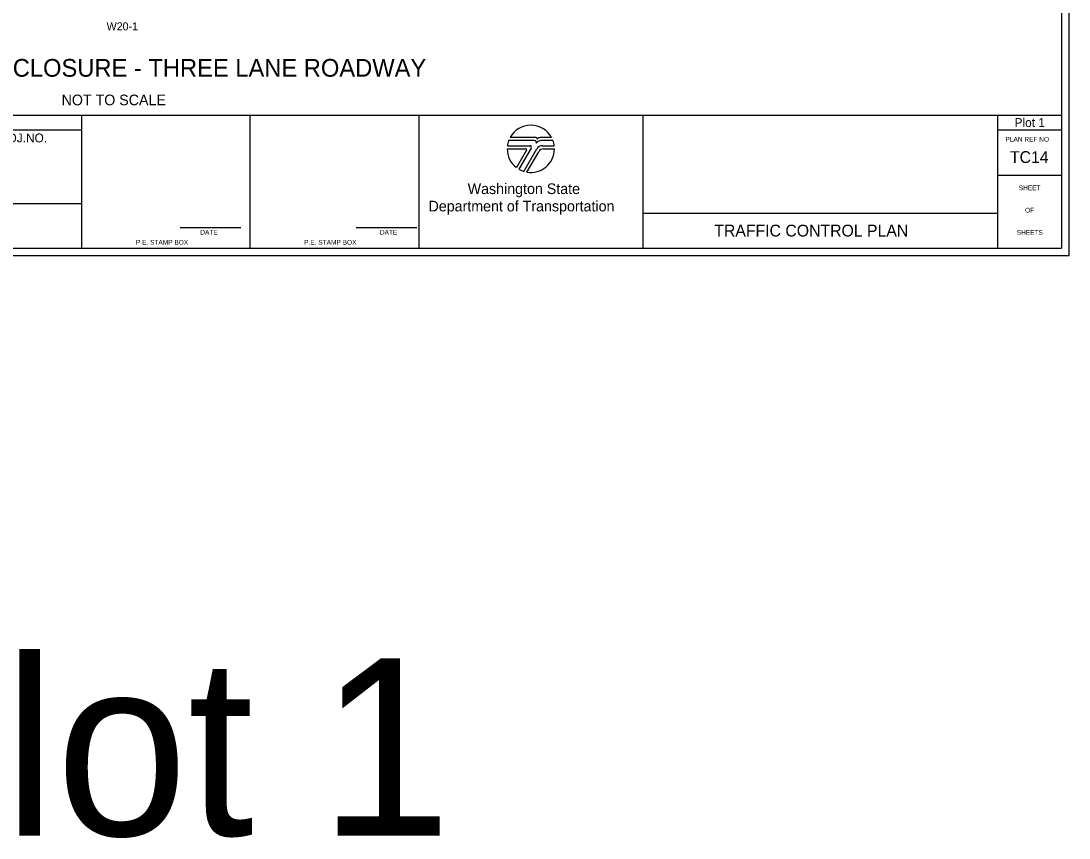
# Model space of a CAD drawing. Extents: x 99988 to 100172, y 99995 to 100047.
# Drawn here: x 100006.94 to 100015.81, y 99995.01 to 100001.92 of the extents above; entities that cross this region are included whole.
import ezdxf

# ---------------------------------------------------------------- set-up
doc = ezdxf.new("R2010")
doc.units = 0
for name, color, linetype in [('SH_DE_DetailHeading1Text', 7, 'Continuous'), ('SH_DE_DetailHeading3Text', 7, 'Continuous'), ('SH_GI_PlotLimits', 7, 'Continuous'), ('SH_GI_SheetBorder', 7, 'Continuous'), ('SH_GI_SheetLocationText', 7, 'Continuous'), ('SH_GI_SheetTextInCells', 7, 'Continuous'), ('SH_GI_TitleBlockText', 7, 'Continuous'), ('SH_GI_WSDOTLogo', 7, 'Continuous'), ('TR_SN_WarningSigns', 7, 'Continuous')]:
    doc.layers.add(name, color=color, linetype=linetype)

msp = doc.modelspace()

# ---------------------------------------------------------------- linework, layer by layer
at = {"layer": 'SH_GI_PlotLimits'}
msp.add_lwpolyline([(99999.3125, 99999.9375), (100015.8125, 99999.9375), (100015.8125, 100010.4375), (99999.3125, 100010.4375)], close=True, dxfattribs=at)
at = {"layer": 'SH_GI_SheetBorder'}
for p, q in [((100015.75, 100010.375), (100015.75, 100000)), ((100000, 100001.1259), (100015.75, 100001.1259)), ((100007.4566, 100000), (100007.4566, 100001.1259)), ((100008.8828, 100000), (100008.8828, 100001.1259)), ((100010.3089, 100001.1259), (100010.3089, 100000)), ((100012.2055, 100001.1259), (100012.2055, 100000)), ((100015.2079, 100001.1259), (100015.2079, 100000)), ((100000, 100001.0008), (100007.4566, 100001.0008)), ((100015.2079, 100001.0008), (100015.75, 100001.0008)), ((100015.2079, 100000.6176), (100015.75, 100000.6176)), ((100007.4566, 100000.3753), (100005.4466, 100000.3753)), ((100012.2055, 100000.2955), (100015.2079, 100000.2955)), ((100008.2903, 100000.1733), (100008.802, 100000.1733)), ((100009.7797, 100000.1733), (100010.2914, 100000.1733)), ((100000, 100000), (100015.75, 100000))]:
    msp.add_line(p, q, dxfattribs=at)
at = {"layer": 'SH_GI_WSDOTLogo'}
for p, q in [((100011.303, 100000.9354), (100011.0815, 100000.9354)), ((100011.433, 100000.9354), (100011.3351, 100000.9354)), ((100011.0572, 100000.84), (100011.2148, 100000.84)), ((100011.059, 100000.8661), (100011.2496, 100000.8661)), ((100011.2894, 100000.9094), (100011.0697, 100000.9094)), ((100011.222, 100000.8277), (100011.1364, 100000.6807)), ((100011.261, 100000.8464), (100011.1567, 100000.6672)), ((100011.1989, 100000.6487), (100011.3089, 100000.839)), ((100011.343, 100000.9094), (100011.3429, 100000.9094)), ((100011.4448, 100000.9094), (100011.343, 100000.9094)), ((100011.3558, 100000.8661), (100011.4555, 100000.8661)), ((100011.3655, 100000.8394), (100011.4572, 100000.8394)), ((100011.2244, 100000.6428), (100011.3242, 100000.8156))]:
    msp.add_line(p, q, dxfattribs=at)
for centre, radius, start, end in [((100011.2572, 100000.84), 0.2, 28.47865, 151.53204), ((100011.303, 100000.9263), 0.00903, 329.87418, 90.00328), ((100011.3352, 100000.9066), 0.0287, 90.00721, 148.16763), ((100011.2572, 100000.84), 0.2, 179.99864, 232.84327), ((100011.2572, 100000.84), 0.2, 159.69598, 172.50569), ((100011.2149, 100000.8318), 0.0082, 329.74356, 90), ((100011.2572, 100000.84), 0.2, 260.54554, 359.80857), ((100011.2497, 100000.853), 0.0131, 329.76834, 90), ((100011.2894, 100000.8946), 0.0148, 327.8418, 89.99855), ((100011.3429, 100000.861), 0.0484, 89.99529, 147.82376), ((100011.3558, 100000.8119), 0.0542, 90, 149.99738), ((100011.3654, 100000.7918), 0.0476, 90, 150.05432), ((100011.2572, 100000.84), 0.2, 7.49431, 20.29406), ((100011.2572, 100000.84), 0.2, 239.79292, 253.0448)]:
    msp.add_arc(centre, radius, start, end, dxfattribs=at)

# ---------------------------------------------------------------- texts
at = {"layer": 'SH_DE_DetailHeading1Text'}
msp.add_text('INTERSECTION LANE CLOSURE - THREE LANE ROADWAY', height=0.15, dxfattribs=at).set_placement((100004.7438, 100001.4505))
at = {"layer": 'SH_DE_DetailHeading3Text'}
msp.add_text('NOT TO SCALE', height=0.09, dxfattribs=at).set_placement((100007.2859, 100001.2089))
at = {"layer": 'SH_GI_SheetBorder'}
msp.add_text('PLAN REF NO', height=0.040032, dxfattribs=at).set_placement((100015.2747, 100000.9008))
at = {"layer": 'SH_GI_SheetLocationText'}
for height, p in [(0.075, (100015.3518, 100001.025)), (1.5, (100005.4547, 99995.0267))]:
    msp.add_text('Plot 1', height=height, dxfattribs=at).set_placement(p)
at = {"layer": 'SH_GI_SheetTextInCells'}
for s, height, p in [('FED.AID PROJ.NO.', 0.07506, (100006.2652, 100000.8945)), ('Washington State', 0.090072, (100010.7229, 100000.4571)), ('SHEET', 0.04003, (100015.3877, 100000.4896)), ('Department of Transportation', 0.090072, (100010.3916, 100000.3101)), ('OF', 0.04003, (100015.4406, 100000.3008)), ('DATE', 0.04003, (100008.4597, 100000.1141)), ('DATE', 0.04003, (100009.9794, 100000.1141)), ('SHEETS', 0.04003, (100015.3698, 100000.112)), ('P.E. STAMP BOX', 0.040032, (100007.915, 100000.0286)), ('P.E. STAMP BOX', 0.040032, (100009.339, 100000.0286))]:
    msp.add_text(s, height=height, dxfattribs=at).set_placement(p)
at = {"layer": 'SH_GI_TitleBlockText'}
for s, p in [('TC14', (100015.3124, 100000.72)), ('TRAFFIC CONTROL PLAN', (100012.8099, 100000.0977))]:
    msp.add_text(s, height=0.1, dxfattribs=at).set_placement(p)
at = {"layer": 'TR_SN_WarningSigns'}
msp.add_text('W20-1', height=0.06768, dxfattribs=at).set_placement((100007.6667, 100001.8429))

doc.saveas('drawing.dxf')
